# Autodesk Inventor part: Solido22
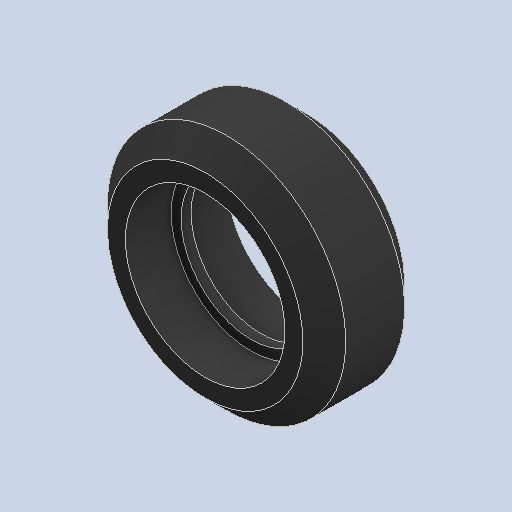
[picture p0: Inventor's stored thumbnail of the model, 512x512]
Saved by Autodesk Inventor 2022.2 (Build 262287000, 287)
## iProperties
Created: 2024-10
Part Number: Solido22
Material: Gomma
Document SubType Name: Modeling
Designer: 18907419
Density: 0.93 g/cm^3
Appearance: Default
Author: 18907419
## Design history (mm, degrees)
feature "Solido22"
node "Solido1"
